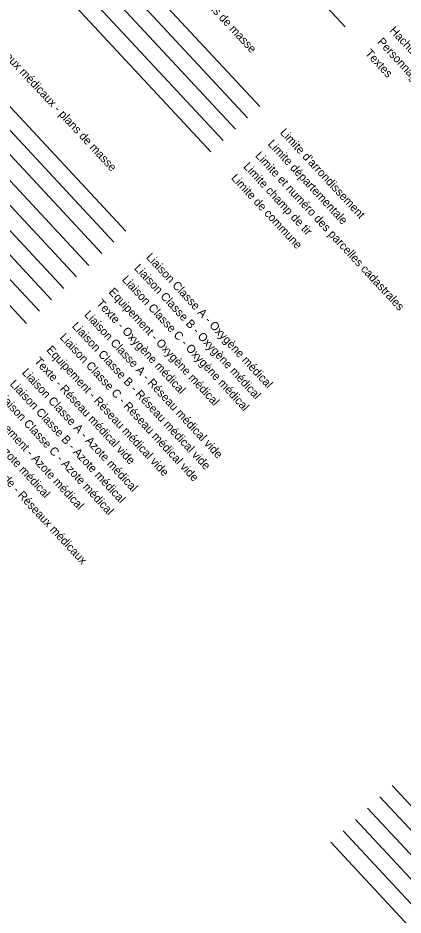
# Model space of a CAD drawing. Extents: x 704383 to 706615, y 7057567 to 7059313.
# Drawn here: x 706475.2 to 706498.3, y 7057729.7 to 7057783.5 of the extents above; entities that cross this region are included whole.
import ezdxf

# ---------------------------------------------------------------- set-up
doc = ezdxf.new("R2010")
doc.units = 0
for name, color, linetype in [('DH_CADRE -CARTOUCHE', 7, 'Continuous'), ('LIM_ADM ARRONDISSEMENT', 7, 'Continuous'), ('LIM_ADM DEPARTEMENT', 7, 'Continuous'), ('LIM_ADM_CADASTRE', 7, 'Continuous'), ('LIM_ADM_CHAMP TIR', 7, 'Continuous'), ('LIM_ADM_COMMUNE', 7, 'Continuous'), ('MASSE_DH_HACHURE-MOTIF', 7, 'Continuous'), ('MASSE_DH_PERSONNAGE_VEHICULES', 7, 'Continuous'), ('MASSE_DH_TEXTE', 7, 'Continuous'), ('R_CF_ALT_POINT', 7, 'Continuous'), ('R_CF_VDI_EQUIP', 7, 'Continuous'), ('R_CF_VDI_LIAISON_CL_A', 7, 'Continuous'), ('R_CF_VDI_LIAISON_CL_B', 7, 'Continuous'), ('R_CF_VDI_LIAISON_CL_C', 7, 'Continuous'), ('R_CF_VDI_TEXTE', 7, 'Continuous'), ('R_MED_ALT_POINT', 7, 'Continuous'), ('R_MED_AZOTE_CANALISATION_CL_A', 7, 'Continuous'), ('R_MED_AZOTE_CANALISATION_CL_B', 7, 'Continuous'), ('R_MED_AZOTE_CANALISATION_CL_C', 7, 'Continuous'), ('R_MED_AZOTE_EQUIP', 7, 'Continuous'), ('R_MED_AZOTE_TEXTE', 7, 'Continuous'), ('R_MED_OXYGENE_CANALISATION_CL_A', 7, 'Continuous'), ('R_MED_OXYGENE_CANALISATION_CL_B', 7, 'Continuous'), ('R_MED_OXYGENE_CANALISATION_CL_C', 7, 'Continuous'), ('R_MED_OXYGENE_EQUIP', 7, 'Continuous'), ('R_MED_OXYGENE_TEXTE', 7, 'Continuous'), ('R_MED_VIDE_CANALISATION_CL_A', 7, 'Continuous'), ('R_MED_VIDE_CANALISATION_CL_B', 7, 'Continuous'), ('R_MED_VIDE_CANALISATION_CL_C', 7, 'Continuous'), ('R_MED_VIDE_EQUIP', 7, 'Continuous'), ('R_MED_VIDE_TEXTE', 7, 'Continuous')]:
    doc.layers.add(name, color=color, linetype=linetype)

msp = doc.modelspace()

# ---------------------------------------------------------------- linework, layer by layer
at = {"layer": 'LIM_ADM ARRONDISSEMENT'}
msp.add_line((706472.838, 7057796.346), (706489.744, 7057778.174), dxfattribs=at)
at = {"layer": 'LIM_ADM DEPARTEMENT'}
msp.add_line((706472.106, 7057795.664), (706489.012, 7057777.492), dxfattribs=at)
at = {"layer": 'LIM_ADM_CADASTRE'}
msp.add_line((706488.28, 7057776.811), (706471.374, 7057794.983), dxfattribs=at)
at = {"layer": 'LIM_ADM_CHAMP TIR'}
msp.add_line((706470.641, 7057794.302), (706487.548, 7057776.13), dxfattribs=at)
at = {"layer": 'LIM_ADM_COMMUNE'}
msp.add_line((706469.909, 7057793.621), (706486.815, 7057775.449), dxfattribs=at)
at = {"layer": 'MASSE_DH_TEXTE'}
msp.add_line((706494.869, 7057782.942), (706477.963, 7057801.114), dxfattribs=at)
at = {"layer": 'R_CF_ALT_POINT'}
msp.add_line((706494.007, 7057734.089), (706510.919, 7057715.91), dxfattribs=at)
at = {"layer": 'R_CF_VDI_EQUIP'}
msp.add_line((706495.471, 7057735.451), (706512.384, 7057717.273), dxfattribs=at)
at = {"layer": 'R_CF_VDI_LIAISON_CL_A'}
msp.add_line((706497.667, 7057737.495), (706514.574, 7057719.323), dxfattribs=at)
at = {"layer": 'R_CF_VDI_LIAISON_CL_B'}
msp.add_line((706496.935, 7057736.814), (706513.841, 7057718.642), dxfattribs=at)
at = {"layer": 'R_CF_VDI_LIAISON_CL_C'}
msp.add_line((706496.203, 7057736.133), (706513.109, 7057717.96), dxfattribs=at)
at = {"layer": 'R_CF_VDI_TEXTE'}
msp.add_line((706494.739, 7057734.77), (706511.651, 7057716.591), dxfattribs=at)
at = {"layer": 'R_MED_OXYGENE_CANALISATION_CL_A'}
msp.add_line((706464.807, 7057788.874), (706481.709, 7057770.706), dxfattribs=at)
at = {"layer": 'R_MED_OXYGENE_CANALISATION_CL_B'}
msp.add_line((706464.098, 7057788.214), (706481, 7057770.046), dxfattribs=at)
at = {"layer": 'R_MED_OXYGENE_CANALISATION_CL_C'}
msp.add_line((706463.365, 7057787.533), (706480.268, 7057769.365), dxfattribs=at)
at = {"layer": 'R_MED_OXYGENE_EQUIP'}
msp.add_line((706479.49, 7057768.641), (706462.588, 7057786.81), dxfattribs=at)
at = {"layer": 'R_MED_OXYGENE_TEXTE'}
msp.add_line((706478.758, 7057767.96), (706461.856, 7057786.128), dxfattribs=at)
at = {"layer": 'R_MED_VIDE_CANALISATION_CL_A'}
msp.add_line((706461.101, 7057785.426), (706477.993, 7057767.269), dxfattribs=at)
at = {"layer": 'R_MED_VIDE_CANALISATION_CL_B'}
msp.add_line((706460.369, 7057784.745), (706477.261, 7057766.588), dxfattribs=at)
at = {"layer": 'R_MED_VIDE_CANALISATION_CL_C'}
msp.add_line((706459.637, 7057784.064), (706476.529, 7057765.907), dxfattribs=at)
at = {"layer": 'R_MED_VIDE_EQUIP'}
msp.add_line((706475.761, 7057765.172), (706458.859, 7057783.34), dxfattribs=at)

# ---------------------------------------------------------------- texts
at = {"layer": 'DH_CADRE -CARTOUCHE'}
for s, p in [('Calques et Styles de traits : Limites administratives - plans de masse', (706475.36, 7057796.249)), (' Calques et Styles de traits: Réseaux médicaux - plans de masse', (706467.712, 7057788.366))]:
    msp.add_text(s, height=0.5, rotation=312.9332, dxfattribs=at).set_placement(p)
at = {"layer": 'LIM_ADM ARRONDISSEMENT'}
msp.add_text("Limite d'arrondissement", height=0.5, rotation=312.9332, dxfattribs=at).set_placement((706490.921, 7057776.587))
at = {"layer": 'LIM_ADM DEPARTEMENT'}
msp.add_text('Limite départementale', height=0.5, rotation=312.9332, dxfattribs=at).set_placement((706490.188, 7057775.906))
at = {"layer": 'LIM_ADM_CADASTRE'}
msp.add_text('Limite et numéro des parcelles cadastrales', height=0.5, rotation=312.9332, dxfattribs=at).set_placement((706489.434, 7057775.204))
at = {"layer": 'LIM_ADM_CHAMP TIR'}
msp.add_text('Limite champ de tir', height=0.5, rotation=312.9332, dxfattribs=at).set_placement((706488.724, 7057774.544))
at = {"layer": 'LIM_ADM_COMMUNE'}
msp.add_text('Limite de commune', height=0.5, rotation=312.9332, dxfattribs=at).set_placement((706487.992, 7057773.863))
at = {"layer": 'MASSE_DH_HACHURE-MOTIF'}
msp.add_text('Hachure et motif', height=0.5, rotation=312.9332, dxfattribs=at).set_placement((706497.487, 7057782.697))
at = {"layer": 'MASSE_DH_PERSONNAGE_VEHICULES'}
msp.add_text('Personnages et Véhicules', height=0.5, rotation=312.9332, dxfattribs=at).set_placement((706496.755, 7057782.015))
at = {"layer": 'MASSE_DH_TEXTE'}
msp.add_text('Textes', height=0.5, rotation=312.9332, dxfattribs=at).set_placement((706496.023, 7057781.334))
at = {"layer": 'R_MED_ALT_POINT'}
msp.add_text('Point et altitude - Réseaux médicaux', height=0.5, rotation=312.9332, dxfattribs=at).set_placement((706471.658, 7057758.666))
at = {"layer": 'R_MED_AZOTE_CANALISATION_CL_A'}
msp.add_text('Liaison Classe A - Azote médical', height=0.5, rotation=312.9332, dxfattribs=at).set_placement((706475.455, 7057762.199))
at = {"layer": 'R_MED_AZOTE_CANALISATION_CL_B'}
msp.add_text('Liaison Classe B - Azote médical', height=0.5, rotation=312.9332, dxfattribs=at).set_placement((706474.723, 7057761.518))
at = {"layer": 'R_MED_AZOTE_CANALISATION_CL_C'}
msp.add_text('Liaison Classe C - Azote médical', height=0.5, rotation=312.9332, dxfattribs=at).set_placement((706473.99, 7057760.837))
at = {"layer": 'R_MED_AZOTE_EQUIP'}
msp.add_text('Equipement - Azote médical', height=0.5, rotation=312.9332, dxfattribs=at).set_placement((706473.19, 7057760.092))
at = {"layer": 'R_MED_AZOTE_TEXTE'}
msp.add_text('Texte - Azote médical', height=0.5, rotation=312.9332, dxfattribs=at).set_placement((706472.458, 7057759.411))
at = {"layer": 'R_MED_OXYGENE_CANALISATION_CL_A'}
msp.add_text('Liaison Classe A - Oxygène médical', height=0.5, rotation=312.9332, dxfattribs=at).set_placement((706482.89, 7057769.116))
at = {"layer": 'R_MED_OXYGENE_CANALISATION_CL_B'}
msp.add_text('Liaison Classe B - Oxygène médical', height=0.5, rotation=312.9332, dxfattribs=at).set_placement((706482.18, 7057768.456))
at = {"layer": 'R_MED_OXYGENE_CANALISATION_CL_C'}
msp.add_text('Liaison Classe C - Oxygène médical', height=0.5, rotation=312.9332, dxfattribs=at).set_placement((706481.448, 7057767.775))
at = {"layer": 'R_MED_OXYGENE_EQUIP'}
msp.add_text('Equipement - Oxygène médical', height=0.5, rotation=312.9332, dxfattribs=at).set_placement((706480.648, 7057767.03))
at = {"layer": 'R_MED_OXYGENE_TEXTE'}
msp.add_text('Texte - Oxygène médical', height=0.5, rotation=312.9332, dxfattribs=at).set_placement((706479.916, 7057766.349))
at = {"layer": 'R_MED_VIDE_CANALISATION_CL_A'}
msp.add_text('Liaison Classe A - Réseau médical vide', height=0.5, rotation=312.9332, dxfattribs=at).set_placement((706479.184, 7057765.668))
at = {"layer": 'R_MED_VIDE_CANALISATION_CL_B'}
msp.add_text('Liaison Classe B - Réseau médical vide', height=0.5, rotation=312.9332, dxfattribs=at).set_placement((706478.451, 7057764.987))
at = {"layer": 'R_MED_VIDE_CANALISATION_CL_C'}
msp.add_text('Liaison Classe C - Réseau médical vide', height=0.5, rotation=312.9332, dxfattribs=at).set_placement((706477.719, 7057764.306))
at = {"layer": 'R_MED_VIDE_EQUIP'}
msp.add_text('Equipement - Réseau médical vide', height=0.5, rotation=312.9332, dxfattribs=at).set_placement((706476.919, 7057763.561))
at = {"layer": 'R_MED_VIDE_TEXTE'}
msp.add_text('Texte - Réseau médical vide', height=0.5, rotation=312.9332, dxfattribs=at).set_placement((706476.187, 7057762.88))

doc.saveas('drawing.dxf')
